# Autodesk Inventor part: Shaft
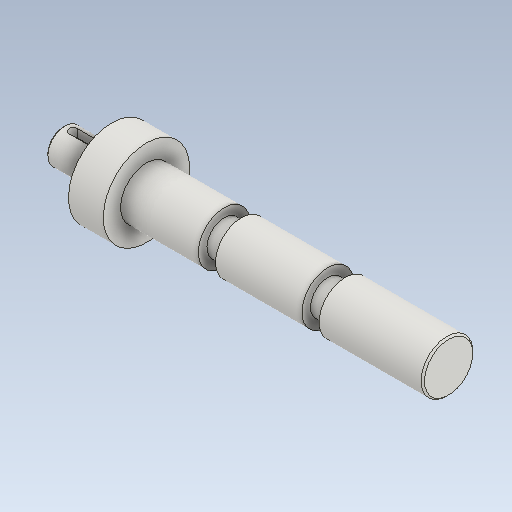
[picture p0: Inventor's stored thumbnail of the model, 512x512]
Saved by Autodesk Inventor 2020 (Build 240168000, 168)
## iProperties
Created: 2019-09
Part Number: Shaft
Material: Steel
Document SubType Name: Modeling
Designer: user
Density: 1 g/cm^3
Appearance: Steel
CustomPartVersion: 1
Author: user
Length: 111,560 mm
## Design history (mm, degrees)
sketch "Main Sketch"
  geometry: L1 (0, 0)-(111.56, 0) reference; L2 (0, 0)-(0, 5); L3 (0, 5)-(14, 5); L4 (14, 5)-(14, 12.5); L5 (24.06, 12.5)-(24.06, 7.5); L6 (14, 12.5)-(24.06, 12.5); L7 (46.56, 7.5)-(46.56, 5); L8 (24.06, 7.5)-(46.56, 7.5); L9 (46.56, 5)-(51.56, 5); L10 (51.56, 5)-(51.56, 7.5); L11 (76.56, 7.5)-(76.56, 5); L12 (51.56, 7.5)-(76.56, 7.5); L13 (76.56, 5)-(81.56, 5); L14 (81.56, 5)-(81.56, 7.5); L15 (111.56, 7.5)-(111.56, 0); L16 (81.56, 7.5)-(111.56, 7.5)
  constraints: 32 end point, 9 horizontal, 8 vertical
  dimensions: "d3" = 10 diameter of L3 L1 (derived); "d4" = 25 diameter of L6 L1 (derived); "d5" = 15 diameter of L8 L1 (derived); "d6" = 10 diameter of L9 L1 (derived); "d7" = 15 diameter of L12 L1 (derived); "d8" = 10 diameter of L13 L1 (derived); "d9" = 15 diameter of L16 L1 (derived)
revolve "Revolution1" sketch "Main Sketch" stored, may be unused: angle "d10" = 0 deg
chamfer "Chamfer1" distance "d11" = 0.5; stored, may be unused: second distance "d12" = 0.5, angle "d13" = 45 deg
node "Keyway1"
chamfer "Chamfer2" distance "d14" = 0.5; stored, may be unused: second distance "d15" = 0.5, angle "d16" = 45 deg
body "Solid1"
feature "iFeature3:1"
other parameters: "d0" = 0, "d1" = 0, "d2" = 0, "Length" = 111.56 [user parameter]
